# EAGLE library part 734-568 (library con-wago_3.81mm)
Serie 734, Federleiste mit abgewinkelten Einlötstiften / Series 734, Female connector with angled solder pins Polzahl / Pole No.: 8 Bemessungsspannung / Rated Voltage: 160 V Nennstrom / Nominal Current: 10 A Lötstiftlänge: / Solder Pin Length: 3.8 mm Farbe / Color: orange / orange Stand: 01.01.2012. Die jeweils aktuellen Daten zu diesem Artikel finden Sie in unserem Produktkatalog, den Sie unter www.wago.com einsehen können. As of: 01/01/2012. Please find the newest data for this article in our product catalogue, which can be viewed under www.wago.com.
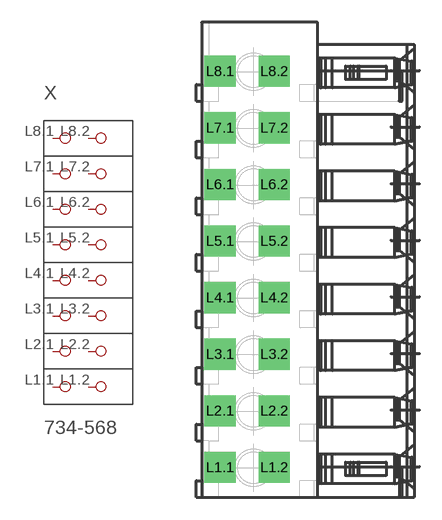
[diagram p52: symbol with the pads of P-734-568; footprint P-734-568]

Designator prefix X

## 734-568  [P-734-568]
L1.1  P1.1
L1.2  P1.2
L2.1  P2.1
L2.2  P2.2
L3.1  P3.1
L3.2  P3.2
L4.1  P4.1
L4.2  P4.2
L5.1  P5.1
L5.2  P5.2
L6.1  P6.1
L6.2  P6.2
L7.1  P7.1
L7.2  P7.2
L8.1  P8.1
L8.2  P8.2

## Footprint P-734-568 (pad centres in mm)
drill 1.4 square: L1.1 -5.909,-13.98; L1.2 -2.259,-13.98; L2.1 -5.909,-10.17; L2.2 -2.259,-10.17; L3.1 -5.909,-6.36; L3.2 -2.259,-6.36; L4.1 -5.909,-2.55; L4.2 -2.259,-2.55; L5.1 -5.909,1.26; L5.2 -2.259,1.26; L6.1 -5.909,5.07; L6.2 -2.259,5.07; L7.1 -5.909,8.88; L7.2 -2.259,8.88; L8.1 -5.909,12.69; L8.2 -2.259,12.69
